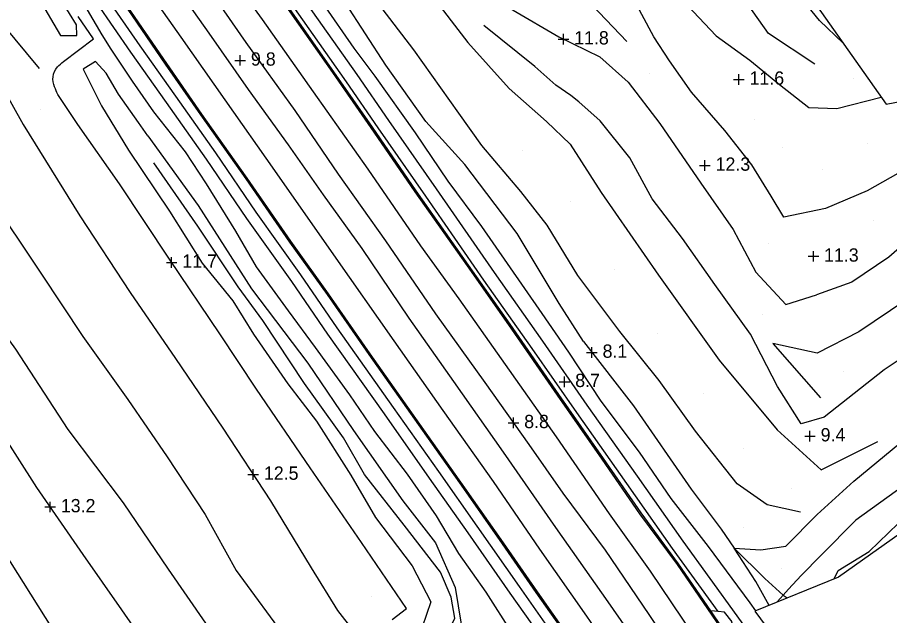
# Model space of a CAD drawing. Extents: x 2316231 to 2323598, y 363169 to 371906.
# Drawn here: x 2319307.8 to 2319635.3, y 369801.3 to 370026.1 of the extents above; entities that cross this region are included whole.
import ezdxf

# ---------------------------------------------------------------- set-up
doc = ezdxf.new("R2010")
doc.units = 0
for name, color, linetype in [('RD_DTM_BkLn1', 7, 'Continuous'), ('RD_DTM_Holes', 7, 'Continuous'), ('RD_DTM_Spot', 7, 'Continuous'), ('RD_DTM_TinHull', 7, 'Continuous'), ('RD_DTM_Void', 7, 'Continuous'), ('RD_EX_H2O', 7, 'Continuous'), ('RD_EX_Road', 7, 'Continuous')]:
    doc.layers.add(name, color=color, linetype=linetype)

msp = doc.modelspace()

# ---------------------------------------------------------------- linework, layer by layer
at = {"layer": 'RD_DTM_BkLn1'}
for p, q in [((2319610.744, 369875.866), (2319602.155, 369873.335)), ((2319595.392, 369809.008), (2319593.173, 369806.429))]:
    msp.add_line(p, q, dxfattribs=at)
for points in [[(2319518.491, 370095.753), (2319536.154, 370074.651), (2319549.373, 370050.767), (2319559.414, 370030.613), (2319570.276, 370019.227), (2319582.845, 370010.006), (2319593.946, 370000.875), (2319605.001, 369992.258), (2319615.528, 369991.916), (2319632.247, 369996.213)], [(2319607.296, 370008.564), (2319589.929, 370020.115), (2319577.7, 370037.332), (2319571.04, 370051.071), (2319564.305, 370064.201), (2319557.968, 370073.438), (2319548.739, 370086.653)], [(2319617.954, 370016.482), (2319608.994, 370025.028), (2319596.909, 370040.06), (2319583.329, 370059.028), (2319575.614, 370074.145), (2319566.359, 370089.293)], [(2319316.007, 370006.945), (2319302.004, 370023.889), (2319288.639, 370040.832), (2319274.709, 370059.947), (2319264.712, 370076.445), (2319281.91, 370084.325), (2319289.391, 370073.183), (2319303.418, 370052.378), (2319315.514, 370033.771), (2319323.994, 370019.358), (2319330.094, 370019.366), (2319330.003, 370023.372), (2319324.675, 370031.857)], [(2319595.617, 369951.088), (2319590.896, 369958.897), (2319583.617, 369970.765), (2319573.419, 369983.615), (2319560.925, 369998.005), (2319552.703, 370009.747), (2319546.83, 370018.861), (2319538.65, 370034.112), (2319532.897, 370045.637), (2319521.267, 370067.639)], [(2319379.619, 370053.033), (2319399.706, 370025.294), (2319418.806, 369998.168), (2319439.375, 369969.065), (2319459.182, 369940.325), (2319473.58, 369920.326), (2319490.986, 369895.74), (2319510.109, 369868.495), (2319530.046, 369839.587), (2319545.379, 369817.996), (2319565.61, 369788.095), (2319585.433, 369760.214), (2319604.885, 369731.928), (2319621.655, 369709.912)], [(2319452.74, 370047.647), (2319462.809, 370035.299), (2319476.892, 370016.675), (2319492.475, 369999.428), (2319506.495, 369986.987), (2319515.343, 369978.466), (2319527.005, 369960.38), (2319548.603, 369929.302), (2319571.341, 369897.251), (2319593.12, 369871.186), (2319609.692, 369856.106), (2319630.924, 369866.797)], [(2319536.662, 370017.101), (2319526.287, 370027.97), (2319517.072, 370037.055), (2319502.362, 370050.048)], [(2319351.401, 370043.955), (2319369.161, 370018.758), (2319385.701, 369995.191), (2319404.266, 369968.558), (2319426.421, 369936.928), (2319449.194, 369904.555), (2319467.594, 369878.424), (2319486.481, 369851.705), (2319503.81, 369826.248), (2319521.512, 369801.076), (2319544.955, 369767.052), (2319558.572, 369748.335), (2319573.687, 369726.172)], [(2319373.932, 370045.125), (2319393.586, 370016.755), (2319411.893, 369991.126), (2319428.181, 369967.238), (2319446.038, 369942.208), (2319464.813, 369914.738), (2319483.346, 369888.941), (2319499.864, 369865.625), (2319512.647, 369847.342), (2319528.53, 369825.903), (2319544.983, 369801.752), (2319563.682, 369773.315), (2319582.544, 369746.525)], [(2319365.977, 370039.641), (2319379.673, 370020.195), (2319394.423, 369998.977), (2319409.414, 369978.283), (2319422.541, 369959.39), (2319437.105, 369939.271), (2319454.718, 369913.12), (2319471.543, 369889.277), (2319490.192, 369862.739), (2319509.894, 369834.453), (2319529.502, 369806.441), (2319543.304, 369786.684), (2319559.749, 369763.249), (2319576.32, 369738.823)], [(2319479.478, 370036.274), (2319493.943, 370028.844), (2319511.115, 370018.811), (2319526.462, 370011.317), (2319537.155, 370001.735), (2319549.094, 369986.286), (2319564.493, 369963.787), (2319576.661, 369946.403), (2319585.076, 369930.399), (2319596.399, 369918.271), (2319607.875, 369921.902)], [(2319577.007, 369826.713), (2319586.975, 369826.091), (2319596.391, 369827.451), (2319608.184, 369839.366), (2319621.982, 369851.867), (2319639.239, 369866.139), (2319655.119, 369877.011), (2319673.826, 369886.431), (2319695.805, 369900.804), (2319714.969, 369916.573), (2319729.244, 369927.824), (2319745.487, 369941.718), (2319763.467, 369954.221), (2319784.484, 369967.283), (2319811.016, 369984.096), (2319825.887, 369992.972), (2319840.756, 369997.015), (2319856.622, 370011.776), (2319869.101, 370023.677), (2319884.997, 370034.416)], [(2319585.177, 369803.165), (2319583.025, 369806.171), (2319567.308, 369827.299), (2319553.329, 369845.325), (2319541.389, 369862.756), (2319527.07, 369881.895), (2319514.836, 369900.366), (2319504.802, 369914.91), (2319491.854, 369933.623), (2319482.234, 369947.556), (2319469.528, 369964.586), (2319457.34, 369982.734), (2319442.09, 370004.098), (2319434.183, 370014.584), (2319422.55, 370031.381)], [(2319520.336, 369904.359), (2319511.244, 369918.66), (2319495.494, 369944.932), (2319475.839, 369970.795), (2319461.207, 369987.035), (2319446.17, 370008.147), (2319430.871, 370031.671)], [(2319601.85, 369840.235), (2319589.342, 369842.891), (2319578.115, 369850.793), (2319562.475, 369870.583), (2319548.776, 369889.635), (2319534.095, 369908.059), (2319518.222, 369929.08), (2319506.767, 369948.096), (2319496.902, 369960.646), (2319482.239, 369977.972), (2319473.613, 369990.133), (2319456.598, 370013.989), (2319441.922, 370033.416)], [(2319493.676, 369794.561), (2319483.85, 369810.083), (2319473.53, 369824.677), (2319465.153, 369838.806), (2319454.337, 369854.417), (2319442.055, 369870.501), (2319432.578, 369884.29), (2319419.78, 369902.119), (2319409.54, 369915.913), (2319397.498, 369932.377), (2319389.774, 369945.775), (2319378.79, 369963.535), (2319370.892, 369975.597), (2319358.962, 369990.605), (2319350.93, 370002.226), (2319342.936, 370014.193), (2319339.598, 370019.618), (2319334.109, 370028.97)], [(2319925.691, 370028.793), (2319907.351, 370020.389), (2319887.402, 370011.931), (2319869.004, 369999.014), (2319853.506, 369990.433), (2319843.241, 369987.717), (2319823.416, 369974.784), (2319807.564, 369962.9), (2319786.646, 369947.072), (2319750.33, 369924.855), (2319730.832, 369912.134), (2319713.704, 369899.076), (2319695.706, 369887.269), (2319682.231, 369878.769), (2319665.701, 369868.507), (2319643.68, 369852.302), (2319622.642, 369837.216), (2319609.662, 369824.071), (2319602.127, 369816.429), (2319597.358, 369811.292), (2319595.392, 369809.008)], [(2319816.26, 370028.394), (2319813.245, 370026.533), (2319805.686, 370016.126), (2319794.03, 370007.212), (2319784.935, 370000.005), (2319776.598, 369993.998), (2319761.772, 369987.268), (2319749.018, 369981.282), (2319733.821, 369972.351), (2319714.419, 369963.115), (2319697.208, 369956.093), (2319677.876, 369947.576), (2319660.684, 369937.531), (2319651.038, 369927.955), (2319641.455, 369919.817), (2319623.793, 369907.942), (2319608.163, 369899.98)], [(2319602.155, 369873.335), (2319593.277, 369887.407), (2319583.15, 369907.097), (2319569.724, 369925.705), (2319557.52, 369943.078), (2319546.139, 369957.904), (2319537.829, 369973.358), (2319526.622, 369987.299), (2319518.614, 369994.348), (2319515.678, 369996.751), (2319509.957, 370000.709), (2319502.139, 370007.637), (2319483.002, 370023.065)], [(2319294.574, 370013.123), (2319309.889, 369985.933), (2319331.255, 369951.586), (2319350.142, 369922.755), (2319367.129, 369897.992), (2319384.932, 369871.816), (2319402.789, 369844.47), (2319418.091, 369819.263), (2319428.021, 369803.215), (2319439.558, 369788.412)], [(2319356.683, 369981.629), (2319353.248, 369986.648), (2319345.712, 369997.324), (2319341.11, 370005.19), (2319337.087, 370009.604), (2319332.487, 370006.668), (2319339.386, 369992.904), (2319349.457, 369976.211), (2319364.842, 369953.319), (2319377.105, 369933.714), (2319388.706, 369919.651), (2319396.47, 369907.065), (2319409.288, 369888.435), (2319420.076, 369874.377), (2319433.028, 369854.111), (2319442.243, 369838.163), (2319456.042, 369819.97), (2319463.073, 369806.492), (2319459.728, 369796.925)], [(2319712.141, 370008.497), (2319708.062, 370006.121), (2319697.158, 369999.227), (2319682.004, 369989.779), (2319667.403, 369983.228), (2319654.002, 369973.749), (2319641.367, 369969.145), (2319626.916, 369961.009), (2319611.281, 369954.295), (2319595.617, 369951.088)], [(2319757.034, 370007.065), (2319739.653, 369999.73), (2319723.877, 369991.903), (2319708.015, 369982.492), (2319693.599, 369974.592), (2319680.146, 369965.978), (2319664.231, 369957.31), (2319645.941, 369945.55), (2319635.081, 369936.081), (2319621.219, 369926.57), (2319607.875, 369921.902)], [(2319277.567, 369988.754), (2319296.763, 369959.479), (2319316.518, 369930.01), (2319332.269, 369906.257), (2319349.202, 369882.58), (2319363.95, 369860.992), (2319378.28, 369839.299), (2319389.903, 369818.241), (2319409.517, 369791.483), (2319424.85, 369769.88), (2319440.173, 369748.671), (2319463.34, 369716.475)], [(2319253.523, 369979.08), (2319269.525, 369953.021), (2319287.468, 369928.432), (2319307.01, 369901.483), (2319326.666, 369871.287), (2319347.446, 369843.735), (2319364.361, 369818.793), (2319378.387, 369798.415), (2319391.875, 369780.152), (2319404.184, 369760.225), (2319419.502, 369735.876), (2319432.706, 369718.104), (2319443.711, 369699.843)], [(2319467.192, 369679.522), (2319482.999, 369691.507), (2319495.733, 369699.939), (2319507.325, 369711.576), (2319511.68, 369720.255), (2319513.03, 369727.279), (2319506.625, 369730.595), (2319495.905, 369741.681), (2319483.007, 369758.759), (2319476.937, 369768.926), (2319475.679, 369777.133), (2319470.522, 369786.148), (2319468.723, 369793.499), (2319472.089, 369800.333), (2319470.627, 369808.231), (2319466.629, 369817.587), (2319453.019, 369835.289), (2319438.186, 369854.299), (2319430.177, 369868.116), (2319415.638, 369888.497), (2319399.971, 369912.227), (2319390.667, 369924.917), (2319375.46, 369947.617), (2319358.945, 369971.47)], [(2319731.861, 369950.721), (2319707.615, 369937.056), (2319680.99, 369924.28), (2319657.797, 369909.924), (2319633.313, 369893.709), (2319610.744, 369875.866)], [(2319608.163, 369899.98), (2319591.547, 369903.579), (2319609.393, 369883.097)], [(2319433.154, 369639.964), (2319440.364, 369644.378), (2319435.081, 369652.201), (2319429.019, 369661.698), (2319425.347, 369667.018), (2319424.155, 369671.918), (2319424.713, 369682.694), (2319421.943, 369691.697), (2319402.718, 369719.826), (2319385.966, 369743.8), (2319370.616, 369766.656), (2319358.557, 369786.678), (2319346.924, 369803.534), (2319332.387, 369824.238), (2319314.984, 369849.492), (2319299.558, 369873.602)], [(2319590.066, 369805.161), (2319585.175, 369814.162), (2319577.007, 369826.713)]]:
    msp.add_lwpolyline(points, dxfattribs=at)
at = {"layer": 'RD_DTM_Holes'}
for points in [[(2320011.001, 370049.104), (2319914.062, 370006.451), (2319813.517, 369945.604), (2319677.55, 369859.209), (2319616.153, 369815.81), (2319584.693, 369802.968)], [(2319584.693, 369802.968), (2319660.705, 369700.056), (2319754.308, 369610.998), (2319765.836, 369619.025), (2319691.582, 369734.35), (2319655.747, 369806.941), (2319804.222, 369901.74), (2319913.213, 369967.92), (2320001.585, 370017.55), (2320060.011, 370018.392), (2320136.845, 369980.889), (2320161.642, 369897.111), (2320169.04, 369815.968), (2320165.661, 369789.028), (2320159.965, 369757.242), (2320183.797, 369761.882), (2320186.384, 369801.743), (2320177.996, 369889.534), (2320157.838, 369998.336), (2320127.688, 370035.466)]]:
    msp.add_lwpolyline(points, dxfattribs=at)
at = {"layer": 'RD_DTM_Spot'}
for p, q in [((2319545.289, 370005.035), (2319545.289, 370005.035)), ((2319621.867, 370003.354), (2319621.867, 370003.354)), ((2319316.293, 369991.568), (2319316.293, 369991.568)), ((2319584.781, 369987.877), (2319584.781, 369987.877)), ((2319627.216, 369978.641), (2319627.216, 369978.641)), ((2319497.652, 369976.1), (2319497.652, 369976.1)), ((2319595.098, 369977.222), (2319595.098, 369977.222)), ((2319610.012, 369969.11), (2319610.012, 369969.11)), ((2319515.517, 369957.038), (2319515.517, 369957.038)), ((2319629.284, 369949.707), (2319629.284, 369949.707)), ((2319589.932, 369941.296), (2319589.932, 369941.296)), ((2319606.736, 369936.337), (2319606.736, 369936.337)), ((2319531.89, 369931.276), (2319531.89, 369931.276)), ((2319587.784, 369914.318), (2319587.784, 369914.318)), ((2319548.32, 369907.316), (2319548.32, 369907.316)), ((2319618.194, 369892.958), (2319618.194, 369892.958)), ((2319565.319, 369884.892), (2319565.319, 369884.892)), ((2319580.347, 369864.282), (2319580.347, 369864.282)), ((2319598.685, 369848.99), (2319598.685, 369848.99)), ((2319580.632, 369834.498), (2319580.632, 369834.498)), ((2319594.6, 369819.038), (2319594.6, 369819.038)), ((2319440.739, 369808.663), (2319440.739, 369808.663))]:
    msp.add_line(p, q, dxfattribs=at)
at = {"layer": 'RD_DTM_TinHull'}
for points in [[(2319170.205, 370651.465), (2319634.1, 369993.584), (2319863.396, 370037.401), (2320246.301, 369984.488), (2320646.583, 370063.477), (2321009.446, 370233.043), (2320870.667, 370593.666), (2320743.045, 370821.597), (2320657.552, 371017.902), (2320535.413, 371221.514), (2319782.271, 371232.132)], [(2318500.627, 367718.473), (2317350.395, 369314.708), (2317732.783, 369650.329), (2318062.064, 369676.571), (2318100.376, 368980.922), (2318611.552, 369306.612), (2319043.87, 369561.601), (2319323.163, 369792.894), (2318905.258, 370457.792), (2319170.205, 370651.465)]]:
    msp.add_lwpolyline(points, dxfattribs=at)
at = {"layer": 'RD_DTM_Void'}
for p, q in [((2319510.869, 370017.954), (2319514.869, 370017.954)), ((2319512.869, 370015.954), (2319512.869, 370019.954)), ((2319391.464, 370007.992), (2319391.464, 370011.992)), ((2319389.464, 370009.992), (2319393.464, 370009.992)), ((2319578.736, 370000.829), (2319578.736, 370004.829)), ((2319576.736, 370002.829), (2319580.736, 370002.829)), ((2319565.997, 369968.5), (2319565.997, 369972.5)), ((2319563.997, 369970.5), (2319567.997, 369970.5)), ((2319365.691, 369932.055), (2319365.691, 369936.055)), ((2319604.736, 369936.337), (2319608.736, 369936.337)), ((2319606.736, 369934.337), (2319606.736, 369938.337)), ((2319363.691, 369934.055), (2319367.691, 369934.055)), ((2319521.558, 369900.217), (2319525.558, 369900.217)), ((2319523.558, 369898.217), (2319523.558, 369902.217)), ((2319513.273, 369887.213), (2319513.273, 369891.213)), ((2319511.273, 369889.213), (2319515.273, 369889.213)), ((2319492.1, 369873.76), (2319496.1, 369873.76)), ((2319494.1, 369871.76), (2319494.1, 369875.76)), ((2319605.462, 369866.781), (2319605.462, 369870.781)), ((2319603.462, 369868.781), (2319607.462, 369868.781)), ((2319394.334, 369854.356), (2319398.334, 369854.356)), ((2319396.334, 369852.356), (2319396.334, 369856.356)), ((2319320.057, 369840.131), (2319320.057, 369844.131)), ((2319318.057, 369842.131), (2319322.057, 369842.131))]:
    msp.add_line(p, q, dxfattribs=at)
at = {"layer": 'RD_EX_H2O'}
msp.add_line((2319595.392, 369809.008), (2319596.863, 369807.935), dxfattribs=at)
for points in [[(2319614.482, 369815.128), (2319616.086, 369818.25), (2319627.632, 369825.378), (2319638.598, 369835.948), (2319655.084, 369848.773), (2319673.006, 369861.131), (2319691.232, 369871.07), (2319712.784, 369883.174), (2319732.52, 369898.636), (2319755.415, 369914.129), (2319775.069, 369926.635), (2319801.164, 369943.596), (2319822.07, 369959.311), (2319842.806, 369972.184), (2319860.46, 369982.598), (2319872.792, 369991.846), (2319894.03, 370004.165), (2319918.962, 370013.049), (2319942.923, 370023.5), (2319947.408, 370025.792)], [(2319356.683, 369981.629), (2319375.68, 369955.435), (2319395.712, 369924.079), (2319416.837, 369896.226), (2319434.047, 369870.829), (2319452.53, 369844.483), (2319464.849, 369828.661), (2319472.234, 369811.923), (2319474.453, 369798.1), (2319476.349, 369786.356), (2319481.336, 369774.596), (2319485.998, 369764.616), (2319493.093, 369756.39), (2319493.093, 369756.39)], [(2319520.336, 369904.359), (2319539.212, 369880.088), (2319560.82, 369848.843), (2319572.105, 369833.779), (2319577.007, 369826.713)], [(2319577.007, 369826.713), (2319588.516, 369815.262), (2319595.392, 369809.008)]]:
    msp.add_lwpolyline(points, dxfattribs=at)
at = {"layer": 'RD_EX_Road'}
msp.add_line((2319570.995, 369802.831), (2319568.162, 369803.154), dxfattribs=at)
for points in [[(2319568.162, 369803.154), (2319556.113, 369820.81), (2319541.996, 369839.888), (2319527.855, 369860.393), (2319511.067, 369884.391), (2319492.799, 369910.868), (2319477.229, 369933.012), (2319457.515, 369960.914), (2319441.086, 369984.861), (2319426.583, 370005.685), (2319408.243, 370031.948), (2319385.697, 370064.116), (2319370.966, 370085.41), (2319358.228, 370103.619), (2319356.87, 370105.515)], [(2319513.446, 369794.62), (2319502.66, 369809.935), (2319489.912, 369828.349), (2319475.459, 369849.038), (2319459.997, 369870.82), (2319439.829, 369899.386), (2319424.24, 369921.943), (2319410.092, 369941.69), (2319393.635, 369965.448), (2319376.633, 369989.519), (2319363.422, 370008.571), (2319347.419, 370031.882), (2319332.066, 370053.564), (2319326.043, 370061.936), (2319319.158, 370071.833)], [(2319547.26, 369746.771), (2319534.463, 369764.707), (2319514.918, 369793.399), (2319503.069, 369810.221), (2319490.322, 369828.635), (2319475.868, 369849.326), (2319460.405, 369871.108), (2319440.239, 369899.672), (2319424.649, 369922.231), (2319410.5, 369941.978), (2319394.045, 369965.735), (2319377.043, 369989.806), (2319363.833, 370008.855), (2319347.829, 370032.168), (2319332.473, 370053.855), (2319326.451, 370062.225), (2319319.574, 370072.111)], [(2319552.06, 369725.516), (2319535.509, 369748.906), (2319520.304, 369770.097), (2319508.691, 369787.271), (2319492.847, 369809.795), (2319477.032, 369832.45), (2319462.542, 369852.984), (2319445.601, 369877.136), (2319424.337, 369907.112), (2319410.776, 369926.936), (2319393.912, 369950.567), (2319378.794, 369972.818), (2319363.77, 369994.129), (2319350.387, 370013.068), (2319337.563, 370031.622), (2319327.612, 370045.998), (2319321.084, 370055.244), (2319312.878, 370067.317), (2319312.284, 370068.148)], [(2319551.457, 369733.671), (2319538.944, 369751.354), (2319523.766, 369772.508), (2319512.164, 369789.667), (2319496.302, 369812.216), (2319480.485, 369834.873), (2319465.992, 369855.411), (2319449.048, 369879.567), (2319427.799, 369909.523), (2319414.234, 369929.352), (2319397.374, 369952.978), (2319382.263, 369975.219), (2319367.216, 369996.562), (2319353.845, 370015.484), (2319341.032, 370034.022), (2319331.081, 370048.399), (2319324.102, 370058.235), (2319320.199, 370063.729), (2319315.96, 370069.694)], [(2319659.557, 369671.98), (2319647.832, 369688.146), (2319634.563, 369708.197), (2319622.438, 369725.433), (2319610.978, 369740.698), (2319599.124, 369757.754), (2319581.291, 369782.915), (2319571.934, 369796.74), (2319555.705, 369820.52), (2319541.589, 369839.598), (2319527.444, 369860.108), (2319510.656, 369884.106), (2319492.389, 369910.582), (2319476.821, 369932.724), (2319457.105, 369960.628), (2319440.674, 369984.577), (2319426.173, 370005.399), (2319407.833, 370031.661)], [(2319787.95, 369483.364), (2319765.651, 369521.489), (2319743.921, 369555.334), (2319724.619, 369586.553), (2319703.742, 369618.454), (2319683.639, 369648.938), (2319666.916, 369673.314), (2319654.152, 369693.961), (2319637.209, 369717.522), (2319619.664, 369742.991), (2319602.386, 369766.283), (2319589.715, 369785.039), (2319578.115, 369801.246), (2319557.797, 369829.313), (2319540.638, 369853.73), (2319521.815, 369880.455), (2319505.098, 369904.466), (2319486.949, 369930.198), (2319465.165, 369961.751), (2319447.207, 369987.349), (2319435.384, 370004.687), (2319415.076, 370033.481)], [(2319570.995, 369802.831), (2319553.859, 369826.503), (2319536.682, 369850.946), (2319517.852, 369877.68), (2319501.136, 369901.689), (2319482.981, 369927.429), (2319461.193, 369958.988), (2319443.228, 369984.597), (2319431.408, 370001.929), (2319411.123, 370030.693)], [(2319325.09, 370009.524), (2319336.343, 370018.059), (2319330.586, 370026.446)], [(2319448.511, 369799.825), (2319453.881, 369804.01), (2319436.942, 369828.785), (2319417.728, 369856.901), (2319397.519, 369886.444), (2319383.841, 369907.191), (2319364.902, 369935.223), (2319346.048, 369963.636), (2319330.432, 369985.861), (2319322.924, 369997.157)], [(2319574.642, 369793.631), (2319572.347, 369797.021), (2319568.162, 369803.154)], [(2319574.642, 369793.631), (2319576.207, 369798.914), (2319573.397, 369802.557), (2319570.995, 369802.831)]]:
    msp.add_lwpolyline(points, dxfattribs=at)
msp.add_spline([(2319322.924, 369997.157), (2319321.733, 369999.992), (2319321.144, 370003.827), (2319322.835, 370007.531), (2319325.09, 370009.524)], degree=3, dxfattribs=at)

# ---------------------------------------------------------------- texts
at = {"layer": 'RD_DTM_Void'}
for s, p in [('11.8', (2319516.869, 370015.954)), ('9.8', (2319395.464, 370007.992)), ('11.6', (2319582.736, 370000.829)), ('12.3', (2319569.997, 369968.5)), ('11.3', (2319610.736, 369934.337)), ('11.7', (2319369.691, 369932.055)), ('8.1', (2319527.558, 369898.217)), ('8.7', (2319517.273, 369887.213)), ('8.8', (2319498.1, 369871.76)), ('9.4', (2319609.462, 369866.781)), ('12.5', (2319400.334, 369852.356)), ('13.2', (2319324.057, 369840.131))]:
    msp.add_text(s, height=5, dxfattribs=at).set_placement(p)

doc.saveas('drawing.dxf')
